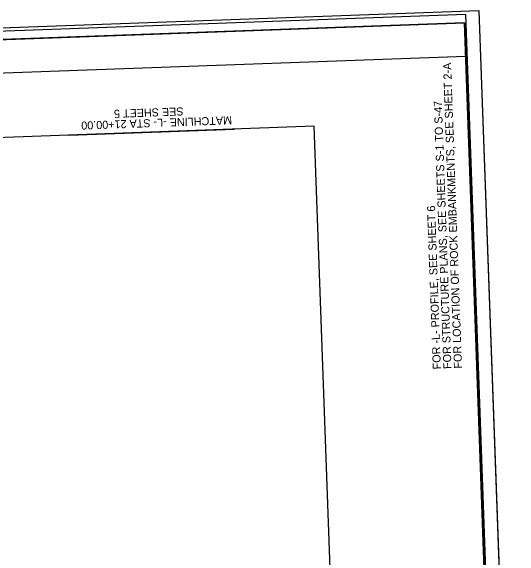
# Model space of a CAD drawing. Extents: x 2065068 to 2066582, y 144283 to 146300.
# Drawn here: x 2065825 to 2066582, y 145217 to 146028 of the extents above; entities that cross this region are included whole.
import ezdxf

# ---------------------------------------------------------------- set-up
doc = ezdxf.new("R2010")
doc.units = 0
for name, color, linetype in [('Matchline', 7, 'Continuous'), ('Matchline Text', 7, 'Continuous'), ('Prop Dimension', 7, 'Continuous'), ('Sheet Clip Boundary CELL', 7, 'Continuous'), ('Sheet Cutting Line CELL', 7, 'Continuous'), ('Sheet Layout Plan Border', 7, 'Continuous'), ('Sheet Plan CELL', 7, 'Continuous'), ('Sheet Plan Layout CELL', 7, 'Continuous'), ('Sheet Plot Border Inside CELL', 7, 'Continuous'), ('Sheet Plot Border Outside CELL', 7, 'Continuous')]:
    doc.layers.add(name, color=color, linetype=linetype)

msp = doc.modelspace()

# ---------------------------------------------------------------- linework, layer by layer
at = {"layer": 'Matchline'}
msp.add_line((2065911.5, 145843.97), (2066157.63, 145852.87), dxfattribs=at)
at = {"layer": 'Sheet Clip Boundary CELL'}
msp.add_lwpolyline([(2066209.26, 144563.12), (2066197.36, 145017.22), (2066304.56, 145076.85), (2066276.35, 145857.16), (2065667.01, 145835.13), (2065670.41, 145741.24), (2065591.32, 145738.38), (2065521, 144770.65), (2065527.51, 144606.5), (2065634.3, 144549.42)], close=True, dxfattribs=at)
at = {"layer": 'Sheet Cutting Line CELL'}
msp.add_line((2066582.43, 144346.04), (2066521.61, 146028.44), dxfattribs=at)
at = {"layer": 'Sheet Layout Plan Border'}
msp.add_lwpolyline([(2066552.11, 144561.57), (2066501.53, 145960.67), (2065663.57, 145930.38), (2065670.41, 145741.24), (2065459.06, 145733.6), (2065502.79, 144523.64)], close=True, dxfattribs=at)
at = {"layer": 'Sheet Plan CELL'}
for points in [[(2065450.41, 145972.73), (2065504.6, 144473.67), (2066553.91, 144511.61), (2066499.73, 146010.64)], [(2066553.91, 144511.61), (2065504.63, 144473.65), (2065457.63, 145772.79), (2065607.59, 145778.22), (2065600.38, 145978.13), (2066499.73, 146010.64)]]:
    msp.add_lwpolyline(points, close=True, dxfattribs=at)
at = {"layer": 'Sheet Plan Layout CELL'}
msp.add_lwpolyline([(2065504.63, 144473.65), (2066553.91, 144511.61), (2066499.73, 146010.63), (2065661.76, 145980.34), (2065670.41, 145741.24), (2065459.06, 145733.6)], close=True, dxfattribs=at)
at = {"layer": 'Sheet Plot Border Inside CELL'}
msp.add_lwpolyline([(2066561.97, 144358.31), (2066501.77, 146023.21), (2065447.47, 145985.11), (2065507.66, 144320.2)], close=True, dxfattribs=at)
at = {"layer": 'Sheet Plot Border Outside CELL'}
msp.add_lwpolyline([(2066582.43, 144346.04), (2066521.61, 146028.44), (2065427.33, 145988.88), (2065488.14, 144306.48)], close=True, dxfattribs=at)

# ---------------------------------------------------------------- texts
at = {"layer": 'Matchline Text'}
for s, p in [('SEE SHEET 5', (2066081.81, 145885.25)), ('MATCHLINE -L- STA 21+00.00', (2066153.97, 145872.12))]:
    msp.add_text(s, height=12, rotation=182.07024, dxfattribs=at).set_placement(p)
at = {"layer": 'Prop Dimension'}
for s, p in [('FOR LOCATION OF ROCK EMBANKMENTS, SEE SHEET 2-A ', (2066496.2, 145497.28)), ('FOR STRUCTURE PLANS, SEE SHEETS S-1 TO S-47', (2066480.48, 145496.71)), ('FOR -L- PROFILE, SEE SHEET 6', (2066464.76, 145496.15))]:
    msp.add_text(s, height=12, rotation=92.07024, dxfattribs=at).set_placement(p)

doc.saveas('drawing.dxf')
